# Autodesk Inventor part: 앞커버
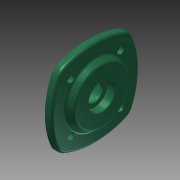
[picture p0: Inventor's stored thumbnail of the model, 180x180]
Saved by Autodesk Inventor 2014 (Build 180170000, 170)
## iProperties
Created: 2015-11
Part Number: 앞커버
Material: 알루미늄 6061
Document SubType Name: Modeling
Designer: mduedu
Density: 2.71 g/cm^3
Mass: 305.843 g
Surface Area: 251.176 cm^2
Volume: 112.857 cm^3
Appearance: 매끄러움 - 짙은 바다 녹색
Author: mduedu
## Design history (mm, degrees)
sketch "스케치1"
  geometry: L1 (50, 50)-(-50, 50); L2 (-50, 50)-(-50, -50); L3 (-50, -50)-(50, -50); L4 (50, -50)-(50, 50); L5 (0, 50)-(0, -50); L6 (50, 0)-(-50, 0); A1 r 90 centre (-40, 0) between (40.415, -40.415) and (40.415, 40.415); A2 r 90 centre (40, 0) between (-40.415, 40.415) and (-40.415, -40.415); A3 r 90 centre (0, -40) between (40.415, 40.415) and (-40.415, 40.415); A4 r 90 centre (0, 40) between (-40.415, -40.415) and (40.415, -40.415); 2 further points
  constraints: 12 end point, 8 point on circle, 5 midpoint, 4 centre point, 2 horizontal alignment, 2 parallel, 2 perpendicular, 2 symmetric about line, 2 tangent, 2 vertical alignment, 1 equal radius, 1 horizontal, 2 other
  dimensions: "d0" = 100 distance of L3.end L1.start; "d2" = 90 radius of A1
extrude "돌출1" new body sketch "스케치1" distance "d3" = 8; taper "d4" = 0 deg
sketch "스케치2"
  geometry: C1 r 35 at (0, 0); 1 further point
  constraints: 1 centre point, 1 coincident
  dimensions: "d5" = 70 diameter of C1
extrude "돌출2" join sketch "스케치2" distance "d6" = 7; taper "d7" = -30 deg
sketch "스케치3"
  geometry: L1 (0, 0)-(0, 40); L2 (0, 0)-(-28.284, 28.284); A1 r 40 centre (0, 0) between (0, 40) and (-28.284, 28.284); 2 further points
  constraints: 4 end point, 2 coincident, 2 point on circle, 1 centre point, 1 vertical
  dimensions: "d8" = 80 diameter of A1; "d9" = 45 deg angle of L1 L2
hole "구멍1" sketch "스케치3" at (-28.284, 28.284) diameter "d11" = 4.5; stored, may be unused: countersink angle "d15" = 90 deg, drill point angle "d17" = 118 deg; dims "d12" = 6, "d13" = 8, "d14" = 4.4, "d16" = 8
sketch "스케치4"
  geometry: C1 r 35 at (0, 0); 1 further point
  constraints: 1 centre point, 1 coincident
  dimensions: "d21" = 70 diameter of C1
extrude "돌출3" join sketch "스케치4" distance "d23" = 12; taper "d24" = 0 deg
hole "구멍2" diameter "d27" = 30; stored, may be unused: countersink angle "d31" = 90 deg, drill point angle "d33" = 0 deg; dims "d25" = 10, "d26" = 10, "d28" = 6, "d29" = 40, "d30" = 12, "d32" = 15
fillet "모깎기2" dims "d35" = 15
fillet "모깎기3" dims "d36" = 3
fillet "모깎기4" dims "d37" = 3
fillet "모깎기5" dims "d38" = 0.3
chamfer "모따기1" distance "d39" = 1; stored, may be unused: second distance "d40" = 2, angle "d41" = 45 deg
hole "구멍3" diameter "d44" = 20; stored, may be unused: countersink angle "d48" = 90 deg, drill point angle "d50" = 118 deg; dims "d45" = 6, "d46" = 30, "d47" = 8.7, "d49" = 8, "d55" = 10, "d56" = 10
fillet "모깎기6" dims "d51" = 0.3
chamfer "모따기2" distance "d52" = 0.7; stored, may be unused: second distance "d53" = 2, angle "d54" = 30 deg
node "솔리드1"
pattern_circular "원형 패턴1" dims angle "d19" = 360 deg
